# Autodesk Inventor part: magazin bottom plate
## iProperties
Created: 2006-04
Part Number: magazin bottom plate
Document SubType Name: Modeling
Designer: Калинин
Author: Калинин
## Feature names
1. Выдавливание1 [Extrusion]
2. Выдавливание2 [Extrusion]
3. Выдавливание3 [Extrusion]
4. Выдавливание4 [Extrusion]
5. По сечениям1
6. Сопряжение1 [Fillet]
7. Сопряжение2 [Fillet]
8. Сопряжение3 [Fillet]
9. Сопряжение4 [Fillet]
10. Сопряжение5 [Fillet]
11. Сопряжение6 [Fillet]
12. Сопряжение7 [Fillet]
13. Сопряжение8 [Fillet]
14. Сопряжение9 [Fillet]
15. Сопряжение10 [Fillet]
16. Сопряжение11 [Fillet]
17. Сопряжение12 [Fillet]
18. Сопряжение13 [Fillet]
19. Сопряжение14 [Fillet]
20. Сопряжение15 [Fillet]
21. Сопряжение16 [Fillet]
22. Сопряжение17 [Fillet]
23. Сопряжение18 [Fillet]
24. Сопряжение19 [Fillet]
25. Сопряжение20 [Fillet]
26. Сопряжение21 [Fillet]
27. Сопряжение22 [Fillet]
28. Сопряжение23 [Fillet]
29. Сопряжение24 [Fillet]
